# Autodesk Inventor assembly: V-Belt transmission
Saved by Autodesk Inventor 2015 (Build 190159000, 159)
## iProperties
Created: 2015-03
Part Number: V-Belt transmission
Document SubType Name: Assembly
Designer: Uglješa
ClientObjectVersion: 1
Author: Uglješa
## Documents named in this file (4)
- C:\Users\Uglješa\Desktop\Turbokompr\Assembly1\Design Accelerator\V-Belt transmission2.iam
- C:\Users\Uglješa\Desktop\Turbokompr\Assembly1\Design Accelerator\V-Belt2.ipt
- C:\Users\Uglješa\Desktop\Turbokompr\Assembly1\Design Accelerator\Grooved Pulley12.ipt
- C:\Users\Uglješa\Desktop\Turbokompr\Assembly1\Design Accelerator\Grooved Pulley21.ipt
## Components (8 placed, 3 different names)
1. Grooved Pulley1:1 — Flush:1, Rotation:1
2. Grooved Pulley2:1 — Flush:2, Rotation:1
3. V-Belt:1 — Flush:1, Flush:2
4. V-Belt:2
5. V-Belt:3
6. V-Belt:4
7. V-Belt:5
8. V-Belt:6
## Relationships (3: Flush 2, RelateRotation 1)
- Flush:1: Grooved Pulley1:1 ↔ V-Belt:1
- Flush:2: Grooved Pulley2:1 ↔ V-Belt:1
- Rotation:1 [RelateRotation]: Grooved Pulley1:1 ↔ Grooved Pulley2:1
